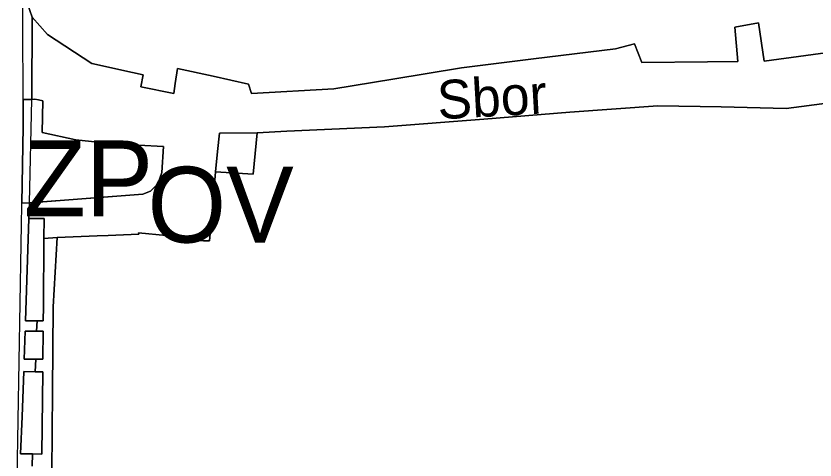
# Model space of a CAD drawing. Extents: x -555509 to -553005, y -1186756 to -1182560.
# Drawn here: x -554599.6 to -554451.9, y -1184774.5 to -1184692.3 of the extents above; entities that cross this region are included whole.
import ezdxf

# ---------------------------------------------------------------- set-up
doc = ezdxf.new("R2010")
doc.units = 0
for name, color, linetype in [('Level 15', 7, 'Continuous'), ('Level 57', 7, 'Continuous'), ('Level 59', 7, 'Continuous'), ('OBRYS_PLOCH', 7, 'Continuous'), ('stav_BV', 7, 'Continuous'), ('stav_DS', 7, 'Continuous'), ('stav_OV', 7, 'Continuous'), ('stav_PU', 7, 'Continuous'), ('stav_ZP', 7, 'Continuous')]:
    doc.layers.add(name, color=color, linetype=linetype)

msp = doc.modelspace()

# ---------------------------------------------------------------- linework, layer by layer
at = {"layer": 'Level 15'}
for p, q in [((-554596.72, -1184707.79), (-554596.64, -1184692.56)), ((-554598.31, -1184707.81), (-554596.72, -1184707.79)), ((-554598.29, -1184712.84), (-554598.31, -1184707.81)), ((-554598.53, -1184726.98), (-554598.29, -1184712.84)), ((-554597.17, -1184726.9), (-554597.17, -1184726.89)), ((-554597.27, -1184729.82), (-554597.89, -1184748.71)), ((-554597.89, -1184748.71), (-554597.27, -1184729.82)), ((-554594.43, -1184729.82), (-554597.27, -1184729.82)), ((-554594.47, -1184733.49), (-554594.43, -1184729.82)), ((-554594.58, -1184746.08), (-554594.47, -1184733.49)), ((-554594.61, -1184748.74), (-554594.58, -1184746.08)), ((-554597.89, -1184748.71), (-554595.75, -1184748.73)), ((-554595.75, -1184748.73), (-554597.89, -1184748.71)), ((-554595.82, -1184750.64), (-554595.75, -1184748.73)), ((-554595.75, -1184748.73), (-554594.61, -1184748.74)), ((-554597.95, -1184750.62), (-554598.12, -1184755.81)), ((-554598.12, -1184755.81), (-554597.95, -1184750.62)), ((-554595.82, -1184750.64), (-554597.95, -1184750.62)), ((-554597.95, -1184750.62), (-554595.82, -1184750.64)), ((-554594.62, -1184750.65), (-554595.82, -1184750.64)), ((-554594.68, -1184755.84), (-554594.62, -1184750.65)), ((-554598.12, -1184755.81), (-554595.99, -1184755.83)), ((-554595.99, -1184755.83), (-554598.12, -1184755.81)), ((-554596.07, -1184758.14), (-554595.99, -1184755.83)), ((-554595.99, -1184755.83), (-554594.68, -1184755.84)), ((-554596.07, -1184758.14), (-554598.2, -1184758.12)), ((-554598.2, -1184758.12), (-554596.07, -1184758.14)), ((-554594.7, -1184758.15), (-554596.07, -1184758.14)), ((-554594.85, -1184773.37), (-554594.7, -1184758.15)), ((-554598.8, -1184773.34), (-554596.58, -1184773.35)), ((-554596.58, -1184773.35), (-554598.8, -1184773.34)), ((-554596.65, -1184775.6), (-554596.58, -1184773.35)), ((-554596.58, -1184773.35), (-554594.85, -1184773.37))]:
    msp.add_line(p, q, dxfattribs=at)
for points in [[(-554596.64, -1184692.56), (-554597.52, -1184690.07), (-554597.1, -1184688.17), (-554596.82, -1184686.83), (-554595.05, -1184680.03), (-554590.62, -1184669.11), (-554586.04, -1184660.92)], [(-554440.85, -1184697.94), (-554461.27, -1184700.67), (-554462.33, -1184693.61), (-554466.7, -1184694.42), (-554466.14, -1184700.75), (-554471.78, -1184700.79), (-554483.89, -1184700.92), (-554485.25, -1184697.49), (-554488.8, -1184698.44), (-554503.96, -1184700.26), (-554517.28, -1184701.9), (-554529.94, -1184704), (-554540.86, -1184705.8), (-554556.06, -1184706.7), (-554556.64, -1184704.93), (-554563.16, -1184703.5), (-554569.77, -1184702.04), (-554570.18, -1184704.85), (-554570.43, -1184706.67), (-554576.53, -1184705.42), (-554576.09, -1184703.2), (-554578.08, -1184702.78), (-554585.63, -1184701.15), (-554593.79, -1184695.74), (-554596.64, -1184692.56), (-554596.72, -1184707.79), (-554596.14, -1184707.74), (-554595.46, -1184707.82), (-554594.69, -1184708.04), (-554594.81, -1184713.9), (-554588.55, -1184715.27), (-554581.61, -1184715.96), (-554572.38, -1184716.49), (-554572.69, -1184721.3), (-554573.38, -1184723.36), (-554574.75, -1184724.73), (-554576.2, -1184725.27), (-554597.17, -1184726.9), (-554597.17, -1184727.02), (-554597.27, -1184729.82), (-554594.43, -1184729.82), (-554594.47, -1184733.49), (-554592.05, -1184733.32), (-554584.6, -1184733.01), (-554582.58, -1184732.93), (-554576.95, -1184732.7), (-554576.98, -1184732.45), (-554571.87, -1184732.93), (-554571.84, -1184733.18), (-554567.19, -1184733.67), (-554564.96, -1184733.9), (-554563.83, -1184733.91), (-554563.14, -1184725.77), (-554562.76, -1184721.18), (-554562.36, -1184717.41), (-554562.01, -1184714.04), (-554555.04, -1184713.93), (-554549.58, -1184713.64), (-554531.51, -1184712.86), (-554513.14, -1184711.42), (-554497.21, -1184710.13), (-554480.97, -1184708.93), (-554469.25, -1184709.14), (-554457.24, -1184709.42), (-554441.2, -1184707.33)], [(-554597.17, -1184726.89), (-554597.17, -1184726.89), (-554598.53, -1184726.98)], [(-554597.27, -1184729.82), (-554597.17, -1184727.02), (-554597.17, -1184726.9)], [(-554594.47, -1184733.49), (-554594.58, -1184746.08), (-554594.58, -1184746.08)], [(-554592.05, -1184733.32), (-554594.47, -1184733.49)], [(-554594.18, -1184852.76), (-554593.63, -1184837.34), (-554593.32, -1184824.33), (-554593.32, -1184823.01), (-554593.31, -1184819.61), (-554593.3, -1184806.61), (-554593.15, -1184790.69), (-554592.98, -1184776.78), (-554592.89, -1184761.76), (-554592.78, -1184746.13), (-554592.05, -1184733.32)], [(-554594.58, -1184746.08), (-554594.61, -1184748.74)], [(-554595.75, -1184748.73), (-554595.82, -1184750.64)], [(-554594.61, -1184748.74), (-554595.75, -1184748.73)], [(-554595.82, -1184750.64), (-554594.62, -1184750.65)], [(-554594.62, -1184750.65), (-554594.68, -1184755.84)], [(-554595.99, -1184755.83), (-554596.07, -1184758.14)], [(-554594.68, -1184755.84), (-554595.99, -1184755.83)], [(-554598.2, -1184758.12), (-554598.47, -1184766.45), (-554598.8, -1184773.34)], [(-554598.8, -1184773.34), (-554598.47, -1184766.45), (-554598.2, -1184758.12)], [(-554596.07, -1184758.14), (-554594.7, -1184758.15)], [(-554594.7, -1184758.15), (-554594.85, -1184773.37)], [(-554596.58, -1184773.35), (-554596.65, -1184775.6)], [(-554594.85, -1184773.37), (-554596.58, -1184773.35)]]:
    msp.add_lwpolyline(points, dxfattribs=at)
at = {"layer": 'OBRYS_PLOCH'}
for p, q in [((-554598.29, -1184712.84), (-554598.38, -1184689.1)), ((-554596.72, -1184707.79), (-554598.31, -1184707.81)), ((-554598.31, -1184707.81), (-554598.29, -1184712.84)), ((-554599.64, -1184792.05), (-554598.29, -1184712.84)), ((-554598.29, -1184712.84), (-554598.53, -1184726.98)), ((-554555.75, -1184721.58), (-554555.04, -1184713.93)), ((-554555.04, -1184713.93), (-554555.75, -1184721.58)), ((-554555.04, -1184713.93), (-554555.75, -1184721.58)), ((-554562.76, -1184721.18), (-554555.75, -1184721.58)), ((-554555.75, -1184721.58), (-554562.76, -1184721.18)), ((-554555.75, -1184721.58), (-554562.76, -1184721.18)), ((-554576.2, -1184725.27), (-554574.75, -1184724.73)), ((-554597.1, -1184726.89), (-554576.2, -1184725.27)), ((-554598.53, -1184726.98), (-554597.17, -1184726.89)), ((-554597.17, -1184726.89), (-554597.17, -1184726.89)), ((-554597.17, -1184726.89), (-554597.1, -1184726.89))]:
    msp.add_line(p, q, dxfattribs=at)
for points in [[(-554560.44, -1184634.63), (-554572.69, -1184645.88), (-554586.04, -1184660.92), (-554590.62, -1184669.11), (-554595.05, -1184680.03), (-554596.82, -1184686.83), (-554597.1, -1184688.17), (-554597.52, -1184690.07), (-554596.64, -1184692.56), (-554593.79, -1184695.74), (-554585.63, -1184701.15), (-554578.08, -1184702.78), (-554576.09, -1184703.2), (-554576.53, -1184705.42), (-554570.43, -1184706.67), (-554570.18, -1184704.85), (-554569.77, -1184702.04), (-554563.16, -1184703.5), (-554556.64, -1184704.93), (-554556.06, -1184706.7), (-554540.86, -1184705.8), (-554529.94, -1184704)], [(-554529.94, -1184704), (-554517.28, -1184701.9), (-554503.96, -1184700.26), (-554488.8, -1184698.44), (-554485.25, -1184697.49), (-554483.89, -1184700.92), (-554471.78, -1184700.79), (-554466.14, -1184700.75), (-554466.7, -1184694.42), (-554462.33, -1184693.61), (-554461.27, -1184700.67), (-554440.85, -1184697.94)], [(-554437.39, -1184707.24), (-554441.2, -1184707.33), (-554457.24, -1184709.42), (-554469.25, -1184709.14), (-554480.97, -1184708.93), (-554497.21, -1184710.13), (-554513.14, -1184711.42), (-554531.51, -1184712.86), (-554549.58, -1184713.64), (-554555.04, -1184713.93)], [(-554437.39, -1184707.24), (-554441.2, -1184707.33), (-554457.24, -1184709.42), (-554469.25, -1184709.14), (-554480.97, -1184708.93), (-554497.21, -1184710.13), (-554513.14, -1184711.42), (-554531.51, -1184712.86), (-554549.58, -1184713.64), (-554555.04, -1184713.93)], [(-554594.69, -1184708.04), (-554595.46, -1184707.82), (-554596.14, -1184707.74), (-554596.69, -1184707.79), (-554596.72, -1184707.79), (-554596.72, -1184707.79)], [(-554581.61, -1184715.96), (-554588.55, -1184715.27), (-554594.81, -1184713.9), (-554594.69, -1184708.04)], [(-554555.04, -1184713.93), (-554562.01, -1184714.04), (-554562.36, -1184717.41), (-554562.76, -1184721.18)], [(-554572.69, -1184721.3), (-554572.38, -1184716.49), (-554581.61, -1184715.96)], [(-554562.76, -1184721.18), (-554563.14, -1184725.77), (-554563.83, -1184733.91), (-554564.96, -1184733.9), (-554567.19, -1184733.67), (-554571.84, -1184733.18), (-554571.87, -1184732.93), (-554576.98, -1184732.45), (-554576.95, -1184732.7), (-554582.58, -1184732.93), (-554584.6, -1184733.01), (-554592.05, -1184733.32)], [(-554562.76, -1184721.18), (-554563.14, -1184725.77), (-554563.83, -1184733.91), (-554564.96, -1184733.9), (-554567.19, -1184733.67), (-554571.84, -1184733.18), (-554571.87, -1184732.93), (-554576.98, -1184732.45), (-554576.95, -1184732.7), (-554582.58, -1184732.93), (-554584.6, -1184733.01), (-554592.05, -1184733.32)], [(-554574.75, -1184724.73), (-554573.38, -1184723.36), (-554572.69, -1184721.3)], [(-554592.05, -1184733.32), (-554592.78, -1184746.13), (-554592.89, -1184761.76), (-554592.98, -1184776.78), (-554593.15, -1184790.69), (-554593.3, -1184806.61), (-554593.31, -1184819.61), (-554593.32, -1184823.01), (-554593.32, -1184824.33), (-554593.63, -1184837.34), (-554594.18, -1184852.76), (-554594.47, -1184868.16), (-554594.34, -1184882.03), (-554594.3, -1184887.88), (-554594.33, -1184895.9)], [(-554592.05, -1184733.32), (-554592.78, -1184746.13), (-554592.89, -1184761.76), (-554592.98, -1184776.78), (-554593.15, -1184790.69), (-554593.3, -1184806.61), (-554593.31, -1184819.61), (-554593.32, -1184823.01), (-554593.32, -1184824.33), (-554593.63, -1184837.34), (-554594.18, -1184852.76), (-554594.47, -1184868.16), (-554594.34, -1184882.03), (-554594.3, -1184887.88), (-554594.33, -1184895.9)]]:
    msp.add_lwpolyline(points, dxfattribs=at)
at = {"layer": 'stav_BV'}
for p, q in [((-554555.04, -1184713.93), (-554555.75, -1184721.58)), ((-554555.75, -1184721.58), (-554562.76, -1184721.18))]:
    msp.add_line(p, q, dxfattribs=at)
for points in [[(-554560.44, -1184634.63), (-554572.69, -1184645.88), (-554586.04, -1184660.92), (-554590.62, -1184669.11), (-554595.05, -1184680.03), (-554596.82, -1184686.83), (-554597.1, -1184688.17), (-554597.52, -1184690.07), (-554596.64, -1184692.56), (-554593.79, -1184695.74), (-554585.63, -1184701.15), (-554578.08, -1184702.78), (-554576.09, -1184703.2), (-554576.53, -1184705.42), (-554570.43, -1184706.67), (-554570.18, -1184704.85), (-554569.77, -1184702.04), (-554563.16, -1184703.5), (-554556.64, -1184704.93), (-554556.06, -1184706.7), (-554540.86, -1184705.8), (-554529.94, -1184704)], [(-554529.94, -1184704), (-554517.28, -1184701.9), (-554503.96, -1184700.26), (-554488.8, -1184698.44), (-554485.25, -1184697.49), (-554483.89, -1184700.92), (-554471.78, -1184700.79), (-554466.14, -1184700.75), (-554466.7, -1184694.42), (-554462.33, -1184693.61), (-554461.27, -1184700.67), (-554440.85, -1184697.94)], [(-554437.39, -1184707.24), (-554441.2, -1184707.33), (-554457.24, -1184709.42), (-554469.25, -1184709.14), (-554480.97, -1184708.93), (-554497.21, -1184710.13), (-554513.14, -1184711.42), (-554531.51, -1184712.86), (-554549.58, -1184713.64), (-554555.04, -1184713.93)], [(-554562.76, -1184721.18), (-554563.14, -1184725.77), (-554563.83, -1184733.91), (-554564.96, -1184733.9), (-554567.19, -1184733.67), (-554571.84, -1184733.18), (-554571.87, -1184732.93), (-554576.98, -1184732.45), (-554576.95, -1184732.7), (-554582.58, -1184732.93), (-554584.6, -1184733.01), (-554592.05, -1184733.32)], [(-554592.05, -1184733.32), (-554592.78, -1184746.13), (-554592.89, -1184761.76), (-554592.98, -1184776.78), (-554593.15, -1184790.69), (-554593.3, -1184806.61), (-554593.31, -1184819.61), (-554593.32, -1184823.01), (-554593.32, -1184824.33), (-554593.63, -1184837.34), (-554594.18, -1184852.76), (-554594.47, -1184868.16), (-554594.34, -1184882.03), (-554594.3, -1184887.88), (-554594.33, -1184895.9)]]:
    msp.add_lwpolyline(points, dxfattribs=at)
at = {"layer": 'stav_DS'}
for p, q in [((-554598.29, -1184712.84), (-554598.38, -1184689.1)), ((-554599.64, -1184792.05), (-554598.29, -1184712.84))]:
    msp.add_line(p, q, dxfattribs=at)
at = {"layer": 'stav_OV'}
for p, q in [((-554555.75, -1184721.58), (-554555.04, -1184713.93)), ((-554562.76, -1184721.18), (-554555.75, -1184721.58))]:
    msp.add_line(p, q, dxfattribs=at)
msp.add_lwpolyline([(-554555.04, -1184713.93), (-554562.01, -1184714.04), (-554562.36, -1184717.41), (-554562.76, -1184721.18)], dxfattribs=at)
at = {"layer": 'stav_PU'}
for p, q in [((-554596.64, -1184692.56), (-554597.52, -1184690.07)), ((-554597.17, -1184726.9), (-554596.72, -1184707.79)), ((-554597.27, -1184729.82), (-554597.89, -1184748.71)), ((-554597.89, -1184748.71), (-554597.27, -1184729.82)), ((-554594.43, -1184729.82), (-554597.27, -1184729.82)), ((-554594.58, -1184746.08), (-554594.43, -1184729.82)), ((-554594.47, -1184733.49), (-554594.58, -1184746.08)), ((-554594.61, -1184748.74), (-554594.58, -1184746.08)), ((-554594.58, -1184746.08), (-554594.61, -1184748.74)), ((-554597.89, -1184748.71), (-554594.61, -1184748.74)), ((-554595.75, -1184748.73), (-554597.89, -1184748.71)), ((-554594.61, -1184748.74), (-554595.75, -1184748.73)), ((-554597.95, -1184750.62), (-554598.12, -1184755.81)), ((-554598.12, -1184755.81), (-554597.95, -1184750.62)), ((-554594.62, -1184750.65), (-554597.95, -1184750.62)), ((-554597.95, -1184750.62), (-554595.82, -1184750.64)), ((-554595.82, -1184750.64), (-554594.62, -1184750.65)), ((-554594.68, -1184755.84), (-554594.62, -1184750.65)), ((-554594.62, -1184750.65), (-554594.68, -1184755.84)), ((-554598.12, -1184755.81), (-554594.68, -1184755.84)), ((-554595.99, -1184755.83), (-554598.12, -1184755.81)), ((-554594.68, -1184755.84), (-554595.99, -1184755.83)), ((-554594.7, -1184758.15), (-554598.2, -1184758.12)), ((-554598.2, -1184758.12), (-554596.07, -1184758.14)), ((-554596.07, -1184758.14), (-554594.7, -1184758.15)), ((-554594.85, -1184773.37), (-554594.7, -1184758.15)), ((-554594.7, -1184758.15), (-554594.85, -1184773.37)), ((-554598.8, -1184773.34), (-554594.85, -1184773.37)), ((-554596.58, -1184773.35), (-554598.8, -1184773.34)), ((-554594.85, -1184773.37), (-554596.58, -1184773.35))]:
    msp.add_line(p, q, dxfattribs=at)
for points in [[(-554440.85, -1184697.94), (-554461.27, -1184700.67), (-554462.33, -1184693.61), (-554466.7, -1184694.42), (-554466.14, -1184700.75), (-554471.78, -1184700.79), (-554483.89, -1184700.92), (-554485.25, -1184697.49), (-554488.8, -1184698.44), (-554503.96, -1184700.26), (-554517.28, -1184701.9), (-554529.94, -1184704), (-554540.86, -1184705.8), (-554556.06, -1184706.7), (-554556.64, -1184704.93), (-554563.16, -1184703.5), (-554569.77, -1184702.04), (-554570.18, -1184704.85), (-554570.43, -1184706.67), (-554576.53, -1184705.42), (-554576.09, -1184703.2), (-554578.08, -1184702.78), (-554585.63, -1184701.15), (-554593.79, -1184695.74), (-554596.64, -1184692.56)], [(-554592.05, -1184733.32), (-554584.6, -1184733.01), (-554582.58, -1184732.93), (-554576.95, -1184732.7), (-554576.98, -1184732.45), (-554571.87, -1184732.93), (-554571.84, -1184733.18), (-554567.19, -1184733.67), (-554564.96, -1184733.9), (-554563.83, -1184733.91), (-554563.14, -1184725.77), (-554562.76, -1184721.18), (-554562.36, -1184717.41), (-554562.01, -1184714.04), (-554555.04, -1184713.93), (-554549.58, -1184713.64), (-554531.51, -1184712.86), (-554513.14, -1184711.42), (-554497.21, -1184710.13), (-554480.97, -1184708.93), (-554469.25, -1184709.14), (-554457.24, -1184709.42), (-554441.2, -1184707.33), (-554437.39, -1184707.24)], [(-554596.72, -1184707.79), (-554596.14, -1184707.74), (-554595.46, -1184707.82), (-554594.69, -1184708.04), (-554594.81, -1184713.9), (-554588.55, -1184715.27), (-554581.61, -1184715.96), (-554572.38, -1184716.49), (-554572.69, -1184721.3), (-554573.38, -1184723.36), (-554574.75, -1184724.73), (-554576.2, -1184725.27), (-554597.17, -1184726.9)], [(-554597.27, -1184729.82), (-554594.43, -1184729.82), (-554594.47, -1184733.49)], [(-554594.18, -1184852.76), (-554593.63, -1184837.34), (-554593.32, -1184824.33), (-554593.32, -1184823.01), (-554593.31, -1184819.61), (-554593.3, -1184806.61), (-554593.15, -1184790.69), (-554592.98, -1184776.78), (-554592.89, -1184761.76), (-554592.78, -1184746.13), (-554592.05, -1184733.32)], [(-554598.2, -1184758.12), (-554598.47, -1184766.45), (-554598.8, -1184773.34)], [(-554598.8, -1184773.34), (-554598.47, -1184766.45), (-554598.2, -1184758.12)]]:
    msp.add_lwpolyline(points, dxfattribs=at)
at = {"layer": 'stav_ZP'}
for p, q in [((-554596.72, -1184707.79), (-554598.31, -1184707.81)), ((-554598.31, -1184707.81), (-554598.29, -1184712.84)), ((-554598.29, -1184712.84), (-554598.53, -1184726.98)), ((-554576.2, -1184725.27), (-554574.75, -1184724.73)), ((-554597.1, -1184726.89), (-554576.2, -1184725.27)), ((-554598.53, -1184726.98), (-554597.17, -1184726.89)), ((-554597.17, -1184726.89), (-554597.17, -1184726.89)), ((-554597.17, -1184726.89), (-554597.1, -1184726.89))]:
    msp.add_line(p, q, dxfattribs=at)
for points in [[(-554594.69, -1184708.04), (-554595.46, -1184707.82), (-554596.14, -1184707.74), (-554596.69, -1184707.79), (-554596.72, -1184707.79), (-554596.72, -1184707.79)], [(-554581.61, -1184715.96), (-554588.55, -1184715.27), (-554594.81, -1184713.9), (-554594.69, -1184708.04)], [(-554572.69, -1184721.3), (-554572.38, -1184716.49), (-554581.61, -1184715.96)], [(-554574.75, -1184724.73), (-554573.38, -1184723.36), (-554572.69, -1184721.3)]]:
    msp.add_lwpolyline(points, dxfattribs=at)

# ---------------------------------------------------------------- texts
at = {"layer": 'Level 57'}
msp.add_text('Sbor', height=7.174, rotation=3.2368, dxfattribs=at).set_placement((-554521.54, -1184711.47))
at = {"layer": 'Level 59'}
for s, p in [('ZP', (-554598.19, -1184729.37)), ('OV', (-554575.33, -1184734.24))]:
    msp.add_text(s, height=14, dxfattribs=at).set_placement(p)

doc.saveas('drawing.dxf')
